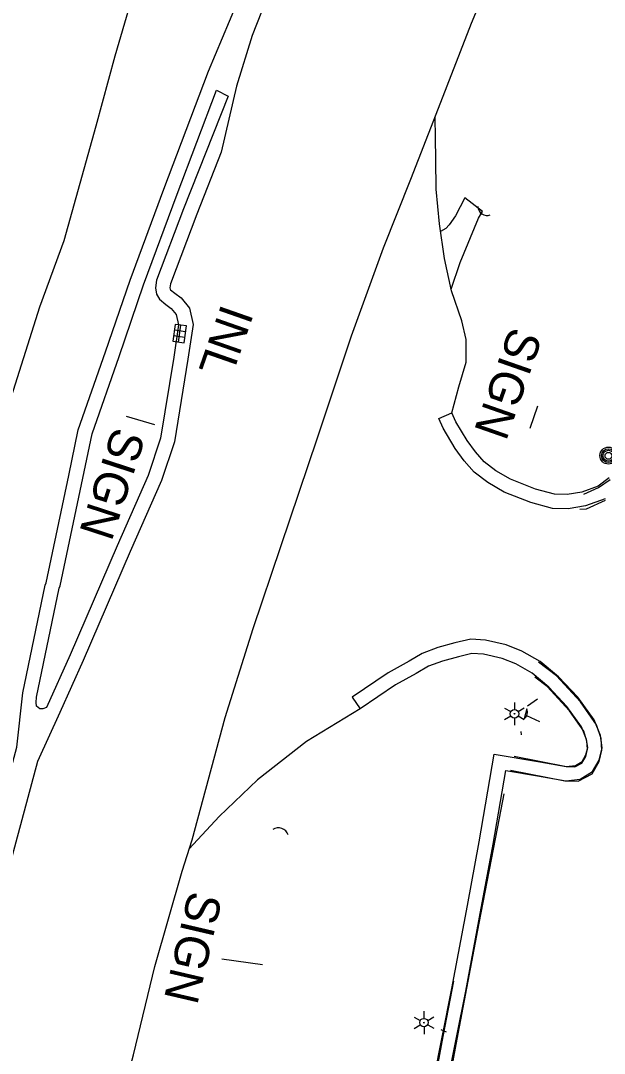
# Model space of a CAD drawing. Extents: x 588843 to 2552415, y 180129 to 269402.
# Drawn here: x 593275.7 to 593378.3, y 185398.1 to 185579.7 of the extents above; entities that cross this region are included whole.
import ezdxf

# ---------------------------------------------------------------- set-up
doc = ezdxf.new("R2010")
doc.units = 0
for name, color, linetype in [('Default', 7, 'Continuous'), ('E_DRN', 7, 'Continuous'), ('E_DRN_Text', 7, 'Continuous'), ('E_DWY', 7, 'Continuous'), ('E_LTG', 7, 'Continuous'), ('E_RDWY', 7, 'Continuous'), ('E_RDWY_C_and_G', 7, 'Continuous'), ('E_SGN', 7, 'Continuous'), ('E_SGN_Text', 7, 'Continuous'), ('E_UTL_MH', 7, 'Continuous')]:
    doc.layers.add(name, color=color, linetype=linetype)

# ---------------------------------------------------------------- blocks, each defined once
blk = doc.blocks.new('CULV2')
at = {"layer": 'E_DRN'}
blk.add_arc((19.7, 14.8), 24.6, 216.8699, 323.1301, dxfattribs=at)
blk = doc.blocks.new('LPOL')
at = {"layer": 'Default'}
for p, q in [((-4, 0), (-1.5, 0)), ((-0.75, 1.3), (-2, 3.46)), ((0.75, 1.3), (2, 3.46)), ((1.5, 0), (4, 0)), ((-2, -3.46), (-0.75, -1.3)), ((2, -3.46), (0.75, -1.3))]:
    blk.add_line(p, q, dxfattribs=at)
for radius in [1.5, 1.5, 1.5, 0.125]:
    blk.add_circle((0, 0), radius, dxfattribs=at)
blk = doc.blocks.new('SIGN')
at = {"layer": 'Default'}
blk.add_text('SIGN', height=12, dxfattribs=at).set_placement((-18.55, -6))
blk = doc.blocks.new('INLO')
at = {"layer": 'E_DRN'}
for p, q in [((2, -4), (2, 0)), ((4, -4), (4, 0)), ((6, -2), (0, -2))]:
    blk.add_line(p, q, dxfattribs=at)
blk.add_lwpolyline([(0, -4), (6, -4), (6, 0), (0, 0), (0, -4)], close=True, dxfattribs=at)
blk = doc.blocks.new('INLT_26')
at = {"layer": 'E_DRN_Text'}
blk.add_text('INL', height=12, dxfattribs=at).set_placement((-11.03, -6))
blk = doc.blocks.new('MHO_3')
at = {"layer": 'E_UTL_MH'}
for centre, radius in [((0.3, -0.4), 9.84), ((0.3, -0.4), 7.98), ((0.2, -0.5), 6.35), ((0.1, -0.5), 3.97)]:
    blk.add_circle(centre, radius, dxfattribs=at)

msp = doc.modelspace()

# ---------------------------------------------------------------- linework, layer by layer
at = {"layer": 'E_DWY'}
for points in [[(593349.22, 185509.76), (593351.5, 185510.77), (593352.73, 185515.32), (593354.01, 185519.66), (593354.04, 185523.64), (593353.25, 185526.93), (593351.42, 185532.18), (593350.2, 185537.89), (593349.31, 185543.98), (593348.72, 185550.06), (593348.69, 185555.28), (593348.62, 185559.12), (593348.56, 185562.76)], [(593378.43, 185495.62), (593375.01, 185494.39), (593371.94, 185493.85), (593369.18, 185493.94), (593365.4, 185494.98), (593360.72, 185496.8), (593357.84, 185498.48), (593355.45, 185500.31), (593353.68, 185502.3), (593352.08, 185504.48), (593349.98, 185508.04), (593349.22, 185509.76)], [(593379.15, 185499.34), (593377.21, 185497.84), (593374.37, 185496.82), (593371.76, 185496.36), (593369.55, 185496.43), (593366.19, 185497.35), (593361.81, 185499.06), (593359.24, 185500.56), (593357.16, 185502.15), (593355.63, 185503.87), (593354.17, 185505.86), (593352.2, 185509.19), (593351.5, 185510.77)], [(593374.69, 185496.42), (593377.28, 185497.59), (593379.34, 185499.04)], [(593374, 185493.8), (593375.16, 185493.89), (593378.52, 185495.41)], [(593350.7, 185392.77), (593353.93, 185409.07), (593356.68, 185423.66), (593358.78, 185434.87), (593361, 185447.84), (593366.53, 185446.93), (593371.51, 185446.04), (593374.08, 185446.33), (593376.22, 185447.66), (593377.41, 185449.64), (593377.94, 185451.81), (593377.6, 185453.99), (593376.49, 185456.74), (593373.62, 185460.72), (593370.26, 185464.33), (593367.03, 185467.01), (593363.8, 185468.86), (593361.07, 185469.92), (593357.42, 185470.76), (593354.82, 185470.97), (593352.04, 185470.28), (593349.06, 185469.49), (593346.28, 185468.43), (593344, 185467.06), (593340.32, 185465.04), (593333.96, 185460.74)], [(593348.25, 185393.25), (593351.48, 185409.54), (593354.22, 185424.12), (593356.32, 185435.31), (593358.96, 185450.71), (593366.95, 185449.39), (593371.59, 185448.56), (593373.24, 185448.75), (593374.38, 185449.46), (593375.07, 185450.6), (593375.39, 185451.92), (593375.17, 185453.32), (593374.29, 185455.52), (593371.69, 185459.13), (593368.54, 185462.51), (593365.6, 185464.94), (593362.72, 185466.6), (593360.33, 185467.53), (593357.04, 185468.28), (593355.03, 185468.45), (593352.66, 185467.86), (593349.83, 185467.1), (593347.38, 185466.17), (593345.25, 185464.89), (593341.62, 185462.91), (593335.36, 185458.67)], [(593361.82, 185447.93), (593371.33, 185446.05), (593373.68, 185445.95), (593376.16, 185447.24), (593377.41, 185449.43), (593377.86, 185451.4), (593377.73, 185453.5), (593376.93, 185455.86), (593374.13, 185459.93), (593369.91, 185464.5), (593366.71, 185466.92)], [(593362.47, 185450.35), (593371.63, 185448.54), (593373.12, 185448.48), (593374.36, 185449.12), (593375.05, 185450.34), (593375.34, 185451.6), (593375.25, 185453.01), (593374.67, 185454.74), (593372.17, 185458.37), (593368.23, 185462.64), (593366.08, 185464.26)], [(593333.99, 185460.76), (593335.36, 185458.67), (593325.97, 185452.96), (593317.35, 185446.19), (593310.58, 185439.74), (593305.32, 185434.05)], [(593320.88, 185296.96), (593326.69, 185296.11), (593328.7, 185296.16), (593330.81, 185297.08), (593332.43, 185298.77), (593333.62, 185301.46), (593336.23, 185316.14), (593340.01, 185336.19), (593343.97, 185356.46), (593348.07, 185377.21), (593352.45, 185400.61), (593356.32, 185420.99), (593359.89, 185439.49), (593360.7, 185443.74)], [(593321.55, 185299.38), (593326.84, 185298.61), (593328.15, 185298.64), (593329.35, 185299.17), (593330.32, 185300.19), (593331.21, 185302.19), (593333.77, 185316.59), (593337.55, 185336.67), (593341.52, 185356.94), (593345.62, 185377.68), (593349.99, 185401.07), (593351.84, 185410.78)]]:
    msp.add_lwpolyline(points, dxfattribs=at)
at = {"layer": 'E_LTG'}
for p, q in [((593364.81, 185459.22), (593366.53, 185460.45)), ((593364.64, 185457.5), (593366.92, 185456.47)), ((593363.62, 185454.68), (593363.67, 185454.13)), ((593349.57, 185402.33), (593350.5, 185401.91))]:
    msp.add_line(p, q, dxfattribs=at)
msp.add_lwpolyline([(593364.67, 185458.68), (593364.21, 185456.94)], dxfattribs=at)
msp.add_arc((593363.28, 185458.12), 1.5, 308.5724, 21.9082, dxfattribs=at)
at = {"layer": 'E_RDWY'}
for points in [[(593308.74, 185570.85), (593317.32, 185591.37), (593327.6, 185615.76), (593340.26, 185645.75), (593355.34, 185680.75), (593355.81, 185681.71), (593358.63, 185685.35), (593360.13, 185684.65), (593359.52, 185680.33), (593346.07, 185649.26), (593327.46, 185605.22), (593316.39, 185577.07), (593313.62, 185568.21), (593310.97, 185556.57)], [(593251.47, 185435.93), (593255.89, 185452.34), (593260.97, 185470.08), (593266.93, 185490.11), (593273.37, 185511.36), (593279.05, 185529.39), (593283.37, 185541.06), (593289, 185561.19), (593292.34, 185573.52), (593296.71, 185588.58), (593301.62, 185606.17), (593306.49, 185623.38), (593312.12, 185642.27), (593315.77, 185654.94), (593317.04, 185659.47)], [(593282.48, 185343.12), (593285.41, 185356.31), (593288.47, 185369.55), (593291.42, 185382.49), (593295.56, 185397.86), (593299.32, 185413.37), (593304.07, 185430.15), (593305.83, 185435.64), (593311.64, 185457.14), (593316.6, 185472.82), (593321.43, 185487.25), (593327.9, 185506.35), (593333.84, 185524.27), (593339.47, 185539.74), (593344.26, 185551.86), (593348.77, 185563.29), (593354.98, 185579.26), (593359.35, 185589.84), (593364.2, 185600.61), (593369.48, 185612.01), (593375.46, 185621.77), (593380.94, 185631.55)], [(593351.35, 185532.51), (593352.98, 185537.19), (593356.18, 185545), (593356.86, 185546.12), (593353.76, 185548.58), (593352.13, 185545.37), (593351.03, 185543.8), (593350.45, 185543.15), (593349.51, 185542.62)], [(593282.59, 185458.06), (593278.67, 185449.43), (593268.63, 185412.33), (593265.78, 185401.62), (593263.57, 185398.58), (593261.91, 185398.97), (593261.86, 185402.83), (593275.04, 185451.95), (593276.09, 185461.5)]]:
    msp.add_lwpolyline(points, dxfattribs=at)
at = {"layer": 'E_RDWY_C_and_G'}
for points in [[(593276.09, 185461.5), (593280.04, 185480.45), (593280.21, 185480.84), (593284.18, 185499.75), (593285.83, 185507.75), (593290.63, 185521.45), (593294.95, 185534.1), (593300.89, 185550.08), (593308.74, 185570.85)], [(593310.97, 185556.57), (593306.69, 185545.69), (593302.04, 185533.43), (593301.94, 185532.73), (593301.97, 185532.51), (593302.05, 185532.4), (593302.78, 185531.76), (593303.9, 185530.94), (593305.37, 185529.14), (593306.01, 185526.3), (593305.12, 185520.16), (593302.72, 185505.66), (593300.45, 185498.84), (593294.95, 185486.35), (593286.68, 185467.2), (593282.59, 185458.06)]]:
    msp.add_lwpolyline(points, dxfattribs=at)
msp.add_lwpolyline([(593282.65, 185480.33), (593286.62, 185499.24), (593288.25, 185507.08), (593293, 185520.64), (593297.31, 185533.26), (593303.23, 185549.2), (593310.14, 185567.48), (593312.16, 185566.44), (593304.35, 185546.59), (593299.6, 185534.05), (593299.42, 185532.72), (593299.58, 185531.62), (593300.13, 185530.75), (593301.21, 185529.81), (593302.17, 185529.11), (593303.06, 185528.02), (593303.47, 185526.21), (593302.65, 185520.55), (593300.29, 185506.26), (593298.12, 185499.74), (593292.66, 185487.35), (593284.4, 185468.21), (593280.23, 185458.9), (593279.6, 185458.68), (593279.07, 185458.69), (593278.51, 185459.17), (593278.42, 185459.8), (593278.49, 185460.77), (593282.49, 185479.94), (593282.65, 185480.33)], close=True, dxfattribs=at)
at = {"layer": 'E_SGN'}
for points in [[(593366.57, 185511.93), (593365.23, 185508.01)], [(593294.28, 185510.14), (593299.25, 185508.67)], [(593318.19, 185413.7), (593311.04, 185414.65)]]:
    msp.add_lwpolyline(points, dxfattribs=at)

# ---------------------------------------------------------------- block references
at = {"layer": 'E_DRN'}
for name, p, xscale, yscale, rotation in [('CULV2', (593356.06, 185547), 0.06714722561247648, 0.06714722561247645, -33.716674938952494), ('INLO', (593304.84, 185526.03), 0.5, 0.5000000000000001, -97.79918601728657), ('CULV2', (593322.72, 185436.53), 0.07235546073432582, 0.07235546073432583, 160.3983797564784)]:
    msp.add_blockref(name, p, dxfattribs=dict(at, xscale=xscale, yscale=yscale, rotation=rotation))
at = {"layer": 'E_DRN_Text', "xscale": 0.49999999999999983, "yscale": 0.4999999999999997, "rotation": -109.30334864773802}
msp.add_blockref('INLT_26', (593312.07, 185523.92), dxfattribs=at)
at = {"layer": 'E_LTG', "xscale": 0.5000000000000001, "yscale": 0.5, "rotation": -89.67337617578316}
for p in [(593362.5, 185457.83), (593346.6, 185403.51)]:
    msp.add_blockref('LPOL', p, dxfattribs=at)
at = {"layer": 'E_SGN_Text'}
for p, xscale, yscale, rotation in [((593361.59, 185516.37), 0.49999999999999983, 0.4999999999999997, -109.30334864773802), ((593292.01, 185498.74), 0.4999999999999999, 0.4999999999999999, -108.04350561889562), ((593306.15, 185417.19), 0.49999999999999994, 0.5000000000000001, -103.13319961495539)]:
    msp.add_blockref('SIGN', p, dxfattribs=dict(at, xscale=xscale, yscale=yscale, rotation=rotation))
at = {"layer": 'E_UTL_MH', "xscale": 0.1524003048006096, "yscale": 0.15240030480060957, "rotation": 72.95030273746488}
msp.add_blockref('MHO_3', (593378.95, 185503.19), dxfattribs=at)

doc.saveas('drawing.dxf')
